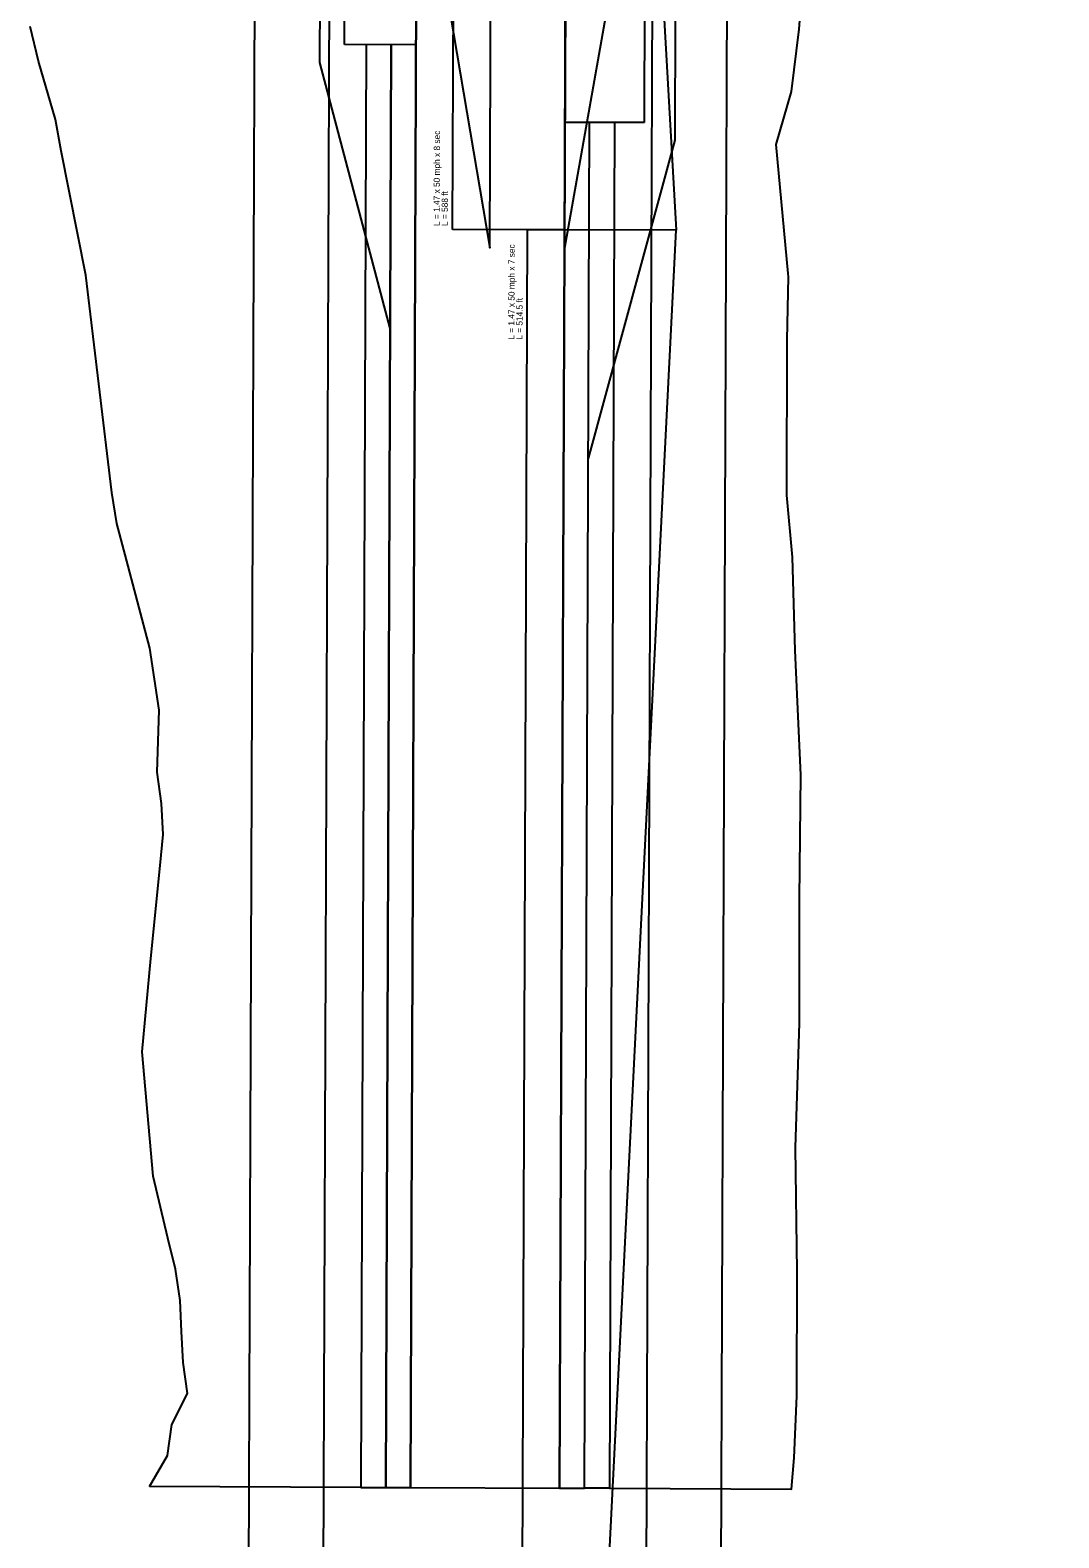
# Model space of a CAD drawing. Extents: x 15359458 to 15360238, y 8797399 to 8799222.
# Drawn here: x 15359858 to 15360023.5, y 8797703.4 to 8797946.1 of the extents above; entities that cross this region are included whole.
import ezdxf

# ---------------------------------------------------------------- set-up
doc = ezdxf.new("R2010")
doc.units = 0
for name, color, linetype in [('Alignment', 7, 'Continuous'), ('MeshTop', 7, 'Continuous'), ('PhoTerrainTriangle', 7, 'Continuous'), ('PhoTerrainVoid', 7, 'Continuous'), ('TL_Barrier', 7, 'Continuous')]:
    doc.layers.add(name, color=color, linetype=linetype)

msp = doc.modelspace()

# ---------------------------------------------------------------- linework, layer by layer
at = {"layer": 'Alignment'}
for p, q in [((15359898.87, 8799211.58), (15359893.01, 8797661.59)), ((15359910.87, 8799211.53), (15359905.01, 8797661.54)), ((15359962.87, 8799211.33), (15359957.01, 8797661.35)), ((15359974.87, 8799211.29), (15359969.01, 8797661.3))]:
    msp.add_line(p, q, dxfattribs=at)
for points in [[(15359906.53, 8798061.15), (15359931.96, 8797911.05), (15359932.52, 8798061.05)], [(15359970.52, 8798060.91), (15359943.96, 8797911.01), (15359944.52, 8798061.01)]]:
    msp.add_lwpolyline(points, close=True, dxfattribs=at)
at = {"layer": 'MeshTop'}
for p, q in [((15359904.6, 8797940.93), (15359904.69, 8797964.32)), ((15359961.77, 8797928.43), (15359961.85, 8797948.43)), ((15359915.91, 8797898.09), (15359904.6, 8797940.93)), ((15359947.83, 8797877.18), (15359961.77, 8797928.43))]:
    msp.add_line(p, q, dxfattribs=at)
at = {"layer": 'PhoTerrainTriangle'}
for p, q in [((15359925.97, 8797914.04), (15359928.19, 8798502.04)), ((15359928.19, 8798502.04), (15359961.97, 8797913.9)), ((15359961.97, 8797913.9), (15359925.97, 8797914.04)), ((15359937.97, 8797913.99), (15359936.02, 8797399.5))]:
    msp.add_line(p, q, dxfattribs=at)
msp.add_lwpolyline([(15359936.02, 8797399.5), (15359961.97, 8797913.9), (15359937.97, 8797913.99)], dxfattribs=at)
at = {"layer": 'PhoTerrainVoid'}
for p, q in [((15359920.33, 8798002.49), (15359919.2, 8797711.49)), ((15359919.2, 8797711.49), (15359920.33, 8798002.49)), ((15359920.33, 8798002.49), (15359919.2, 8797711.49)), ((15359943.2, 8797711.4), (15359944.33, 8798002.4)), ((15359944.33, 8798002.4), (15359943.2, 8797711.4)), ((15359943.2, 8797711.4), (15359944.33, 8798002.4)), ((15359908.57, 8797943.8), (15359908.64, 8797963.8)), ((15359956.88, 8797951.24), (15359956.8, 8797931.24)), ((15359920.1, 8797943.76), (15359908.57, 8797943.8)), ((15359920.1, 8797943.76), (15359908.57, 8797943.8)), ((15359920.1, 8797943.76), (15359908.57, 8797943.8)), ((15359912.08, 8797943.79), (15359911.2, 8797711.52)), ((15359916.08, 8797943.77), (15359915.2, 8797711.5)), ((15359915.2, 8797711.5), (15359916.08, 8797943.77)), ((15359956.8, 8797931.24), (15359944.06, 8797931.29)), ((15359944.06, 8797931.29), (15359956.8, 8797931.24)), ((15359944.06, 8797931.29), (15359956.8, 8797931.24)), ((15359947.2, 8797711.38), (15359948.03, 8797931.27)), ((15359947.2, 8797711.38), (15359948.03, 8797931.27)), ((15359952.03, 8797931.26), (15359951.2, 8797711.37)), ((15359911.2, 8797711.52), (15359915.2, 8797711.5)), ((15359915.2, 8797711.5), (15359919.2, 8797711.49)), ((15359919.2, 8797711.49), (15359943.2, 8797711.4)), ((15359943.2, 8797711.4), (15359947.2, 8797711.38)), ((15359951.2, 8797711.37), (15359947.2, 8797711.38))]:
    msp.add_line(p, q, dxfattribs=at)
at = {"layer": 'TL_Barrier'}
msp.add_line((15359911.2, 8797711.52), (15359877.19, 8797711.65), dxfattribs=at)
for points in [[(15359980, 8797906.92), (15359978.06, 8797927.7), (15359980.51, 8797936.26), (15359981.76, 8797946.25), (15359983.25, 8797966.25), (15359983.81, 8797976.25), (15359984.62, 8797983.74), (15359984.66, 8797999.35), (15359984.9, 8798006.24), (15359985.37, 8798016.24), (15359985.23, 8798026.24), (15359987.28, 8798041.23), (15360023.55, 8798063.6), (15360010.05, 8798071.46)], [(15359877.19, 8797711.65), (15359880.1, 8797716.64), (15359880.76, 8797721.63), (15359883.32, 8797726.62), (15359882.61, 8797731.63), (15359882.34, 8797736.63), (15359882.11, 8797741.63), (15359881.35, 8797746.63), (15359880.15, 8797751.64), (15359877.76, 8797761.65), (15359875.99, 8797781.65), (15359877.41, 8797796.65), (15359878.9, 8797811.64), (15359879.37, 8797816.64), (15359879.1, 8797821.64), (15359878.44, 8797826.64), (15359878.72, 8797836.64), (15359877.26, 8797846.65), (15359873.26, 8797861.66), (15359871.91, 8797866.67), (15359871.15, 8797871.67), (15359866.96, 8797906.69), (15359862.99, 8797926.7), (15359862.04, 8797931.71), (15359859.3, 8797941.1), (15359857.98, 8797946.72)], [(15359951.2, 8797711.37), (15359980.52, 8797711.26), (15359980.94, 8797716.26), (15359981.37, 8797726.25), (15359981.44, 8797746.25), (15359981.17, 8797766.26), (15359981.79, 8797786.25), (15359981.79, 8797806.25), (15359982.03, 8797826.25), (15359981.11, 8797846.26), (15359980.67, 8797861.26), (15359979.76, 8797871.26), (15359979.84, 8797896.26), (15359980.01, 8797906.41), (15359980, 8797906.92)]]:
    msp.add_lwpolyline(points, dxfattribs=at)

# ---------------------------------------------------------------- texts
at = {"layer": 'PhoTerrainTriangle'}
for s, p in [('L = 1.47 x 50 mph x 8 sec', (15359923.9, 8797914.59)), ('L = 588 ft', (15359925.2, 8797914.59)), ('L = 1.47 x 50 mph x 7 sec', (15359935.92, 8797896.28)), ('L = 514.5 ft', (15359937.22, 8797896.28))]:
    msp.add_text(s, height=1, rotation=89.7834, dxfattribs=at).set_placement(p)

doc.saveas('drawing.dxf')
